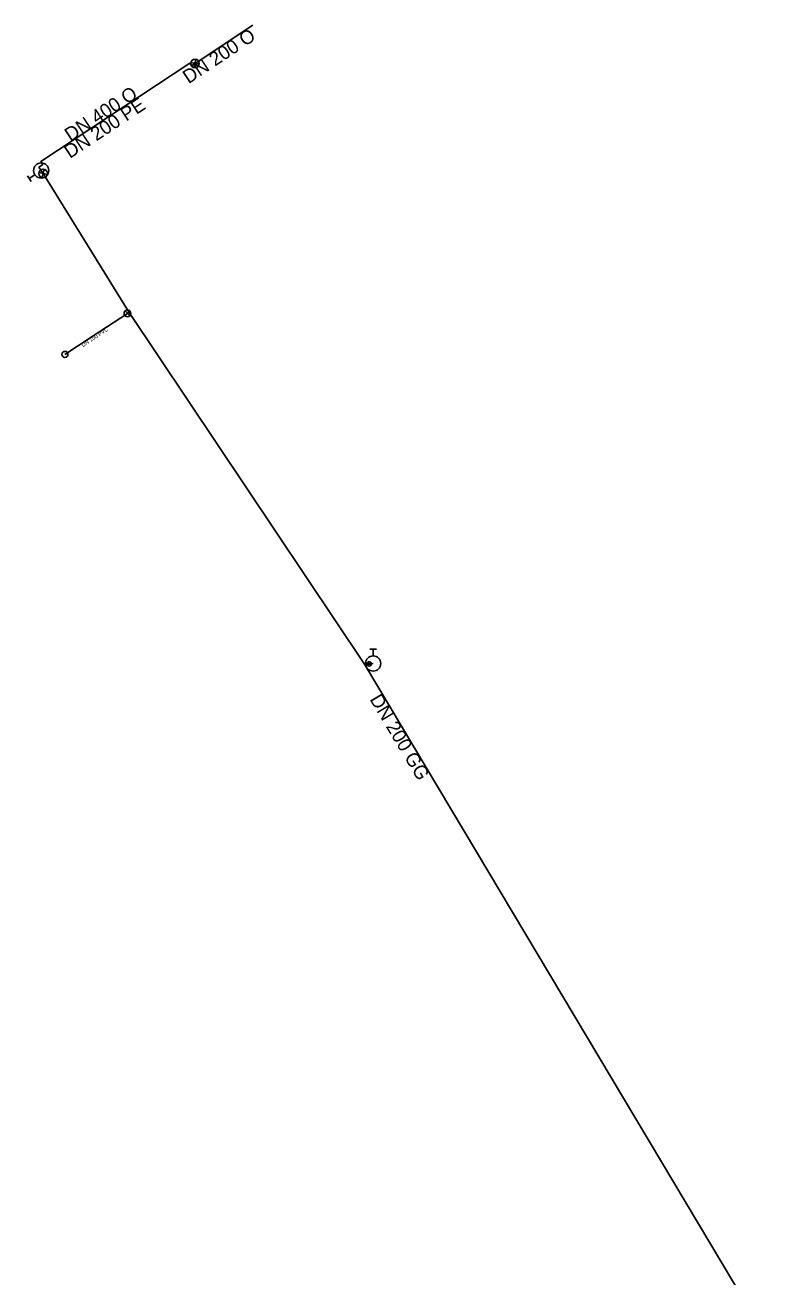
# Model space of a CAD drawing. Extents: x -451555 to -451079, y -1102113 to -1101586.
# Drawn here: x -451165.9 to -451079.7, y -1101925 to -1101779.1 of the extents above; entities that cross this region are included whole.
import ezdxf

# ---------------------------------------------------------------- set-up
doc = ezdxf.new("R2010")
doc.units = 0
for name, color, linetype in [('_hydrantova_odbocka_', 7, 'Continuous'), ('_pripojka_priblizne_', 7, 'Continuous'), ('_voda_smvak_prevzato_z_dokumentace_', 7, 'Continuous'), ('_voda_smvak_priblizne_', 7, 'Continuous'), ('_vodovodni_chranicka_', 7, 'Continuous'), ('Default', 7, 'Continuous'), ('MoLevel 2', 7, 'Continuous'), ('MoLevel 27', 7, 'Continuous'), ('MoLevel 28', 7, 'Continuous'), ('MoLevel 30', 7, 'Continuous'), ('MoLevel 32', 7, 'Continuous'), ('MoLevel 46', 7, 'Continuous'), ('MoLevel 53', 7, 'Continuous'), ('MoLevel 60', 7, 'Continuous')]:
    doc.layers.add(name, color=color, linetype=linetype)

# ---------------------------------------------------------------- blocks, each defined once
blk = doc.blocks.new('_uzaver_')
at = {"layer": 'Default'}
for p, q in [((-0.000035, -0.000035), (0.000035, 0.000035)), ((0.000035, -0.000035), (-0.000035, 0.000035))]:
    blk.add_line(p, q, dxfattribs=at)
for radius in [0.00005, 0.0000025]:
    blk.add_circle((0, 0), radius, dxfattribs=at)
blk = doc.blocks.new('_uzaver_pripojka_')
at = {"layer": 'Default'}
for p, q in [((-0.000035, -0.000035), (0.000035, 0.000035)), ((0.000035, -0.000035), (-0.000035, 0.000035))]:
    blk.add_line(p, q, dxfattribs=at)
for radius in [0.00005, 0.0000025]:
    blk.add_circle((0, 0), radius, dxfattribs=at)
blk = doc.blocks.new('_hydrant_voda_')
at = {"layer": 'Default'}
for p, q in [((-0.0000225, 0.000095), (0.0000225, 0.000095)), ((0, 0.000095), (0, 0.00005))]:
    blk.add_line(p, q, dxfattribs=at)
blk.add_circle((0, 0), 0.00005, dxfattribs=at)
blk = doc.blocks.new('_sachta_voda_')
at = {"layer": 'Default'}
blk.add_circle((0, 0), 0.000035, dxfattribs=at)

msp = doc.modelspace()

# ---------------------------------------------------------------- linework, layer by layer
at = {"layer": '_hydrantova_odbocka_'}
for p, q in [((-451126.34, -1101853.56), (-451125.8, -1101853.52)), ((-451125.8, -1101853.52), (-451125.33, -1101853.47))]:
    msp.add_line(p, q, dxfattribs=at)
at = {"layer": '_pripojka_priblizne_'}
msp.add_line((-451158.1, -1101815.37), (-451161.26, -1101817.44), dxfattribs=at)
msp.add_lwpolyline([(-451153.78, -1101812.57), (-451153.97, -1101812.66), (-451158.1, -1101815.37)], dxfattribs=at)
at = {"layer": '_voda_smvak_prevzato_z_dokumentace_'}
msp.add_line((-451146.1, -1101783.54), (-451139.35, -1101779.06), dxfattribs=at)
msp.add_lwpolyline([(-451079.67, -1101931.88), (-451080.22, -1101930.82), (-451126.34, -1101853.56), (-451153.78, -1101812.57), (-451163.8, -1101796.36), (-451163.8, -1101796.36)], dxfattribs=at)
at = {"layer": '_voda_smvak_priblizne_'}
for p, q in [((-451164.03, -1101796.02), (-451164.3, -1101795.62)), ((-451163.8, -1101796.36), (-451164.03, -1101796.02))]:
    msp.add_line(p, q, dxfattribs=at)
msp.add_lwpolyline([(-451164.3, -1101795.62), (-451163.84, -1101795.3), (-451164.06, -1101794.98), (-451146.72, -1101783.51), (-451146.51, -1101783.81), (-451146.1, -1101783.54)], dxfattribs=at)
at = {"layer": '_vodovodni_chranicka_'}
msp.add_line((-451146.72, -1101783.51), (-451164.06, -1101794.98), dxfattribs=at)

# ---------------------------------------------------------------- block references
at = {"layer": 'MoLevel 27'}
for p, xscale, yscale, rotation in [((-451146.1, -1101783.54), 9999.999999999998, 10000.000000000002, 33.5733216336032), ((-451163.8, -1101796.36), 10000.000000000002, 10000, -58.282993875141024)]:
    msp.add_blockref('_uzaver_', p, dxfattribs=dict(at, xscale=xscale, yscale=yscale, rotation=rotation))
at = {"layer": 'MoLevel 27', "xscale": 5000, "yscale": 5000}
msp.add_blockref('_uzaver_', (-451125.8, -1101853.52), dxfattribs=at)
at = {"layer": 'MoLevel 28', "xscale": 17636.68430335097, "yscale": 17636.684303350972, "rotation": 124.03604710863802}
msp.add_blockref('_hydrant_voda_', (-451164.03, -1101796.02), dxfattribs=at)
at = {"layer": 'MoLevel 28', "xscale": 17636.68430335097, "yscale": 17636.68430335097}
msp.add_blockref('_hydrant_voda_', (-451125.33, -1101853.47), dxfattribs=at)
at = {"layer": 'MoLevel 30', "xscale": 10000, "yscale": 10000}
msp.add_blockref('_sachta_voda_', (-451161.26, -1101817.44), dxfattribs=at)
at = {"layer": 'MoLevel 53', "xscale": 7999.999999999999, "yscale": 7999.999999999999}
msp.add_blockref('_uzaver_pripojka_', (-451153.97, -1101812.66), dxfattribs=at)

# ---------------------------------------------------------------- texts
at = {"layer": 'MoLevel 2'}
msp.add_text('DN 200 PE', height=1.605, rotation=33.4858, dxfattribs=at).set_placement((-451160.68, -1101794.67))
at = {"layer": 'MoLevel 32'}
msp.add_text('DN 150 PVC', height=0.455, rotation=33.2519, dxfattribs=at).set_placement((-451159.15, -1101816.6))
at = {"layer": 'MoLevel 46'}
for s, rotation, p in [('DN 200 O', 33.5733, (-451146.85, -1101785.96)), ('DN 200 GG', 300.8349, (-451125.79, -1101857.63))]:
    msp.add_text(s, height=1.605, rotation=rotation, dxfattribs=at).set_placement(p)
at = {"layer": 'MoLevel 60'}
msp.add_text('DN 400 O', height=1.605, rotation=33.4858, dxfattribs=at).set_placement((-451160.62, -1101792.7))

doc.saveas('drawing.dxf')
